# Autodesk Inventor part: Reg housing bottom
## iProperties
Shininess: 64.0
Angle Display Precision: 2
Document Length Units: 11272
Document Angle Units: 11279
Document Time Units: 11290
Document Mass Units: 11286
Document Length Units Precision: 3
Document Angle Units Precision: 2
Created: 2006-10
Part Number: Reg housing bottom
Document SubType Name: Modeling
Designer: John Croya
Density: 1 g/cm^3
Density: 0.0
Volumn: 0.0
Area: 0.0
PropertySet Name: Model Information
Control State: 0
Master: False
Checked Out: False
Author: John Croya
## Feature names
1. Reg housing bottom [Revolution]
2. External milling 1 [Extrusion]
3. External milling 2 [Circular Pattern]
4. Adjustment screw hole [Revolution]
5. Adjustment screw hole threads
6. Middle section threads
7. Input fitting threads
8. Input exchange ports 1 [Revolution]
9. Input exchange ports 2 [Circular Pattern]
10. Input exchange ports 3 [Circular Pattern]
